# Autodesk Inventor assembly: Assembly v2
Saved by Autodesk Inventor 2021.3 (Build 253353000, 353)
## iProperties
Created: 2022-12
Part Number: Assembly v2
Document SubType Name: Assembly
Designer: AdminForWorker
Title: Assembly v2 v4
Author: AdminForWorker
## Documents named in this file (4)
- c:\worker\convert-fusion-r07-cosv3\tmp\job-1\214\output\files\99734d84-7ac4-47f0-aaa4-b9d74312c45f\fc940e90-a3e4-4232-bff6-c670ae6d8043.iam
- c:\worker\convert-fusion-r07-cosv3\tmp\job-1\214\output\files\99734d84-7ac4-47f0-aaa4-b9d74312c45f\FX29 Load Cell v4.ipt
- c:\worker\convert-fusion-r07-cosv3\tmp\job-1\214\output\files\99734d84-7ac4-47f0-aaa4-b9d74312c45f\Enclosure Top v2 v7.ipt
- c:\worker\convert-fusion-r07-cosv3\tmp\job-1\214\output\files\99734d84-7ac4-47f0-aaa4-b9d74312c45f\Enclosure Bottom v2 v5.ipt
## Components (3 placed, 3 different names)
1. FX29 Load Cell v4:1
2. Enclosure Top v2 v7:1
3. Enclosure Bottom v2 v5:1
